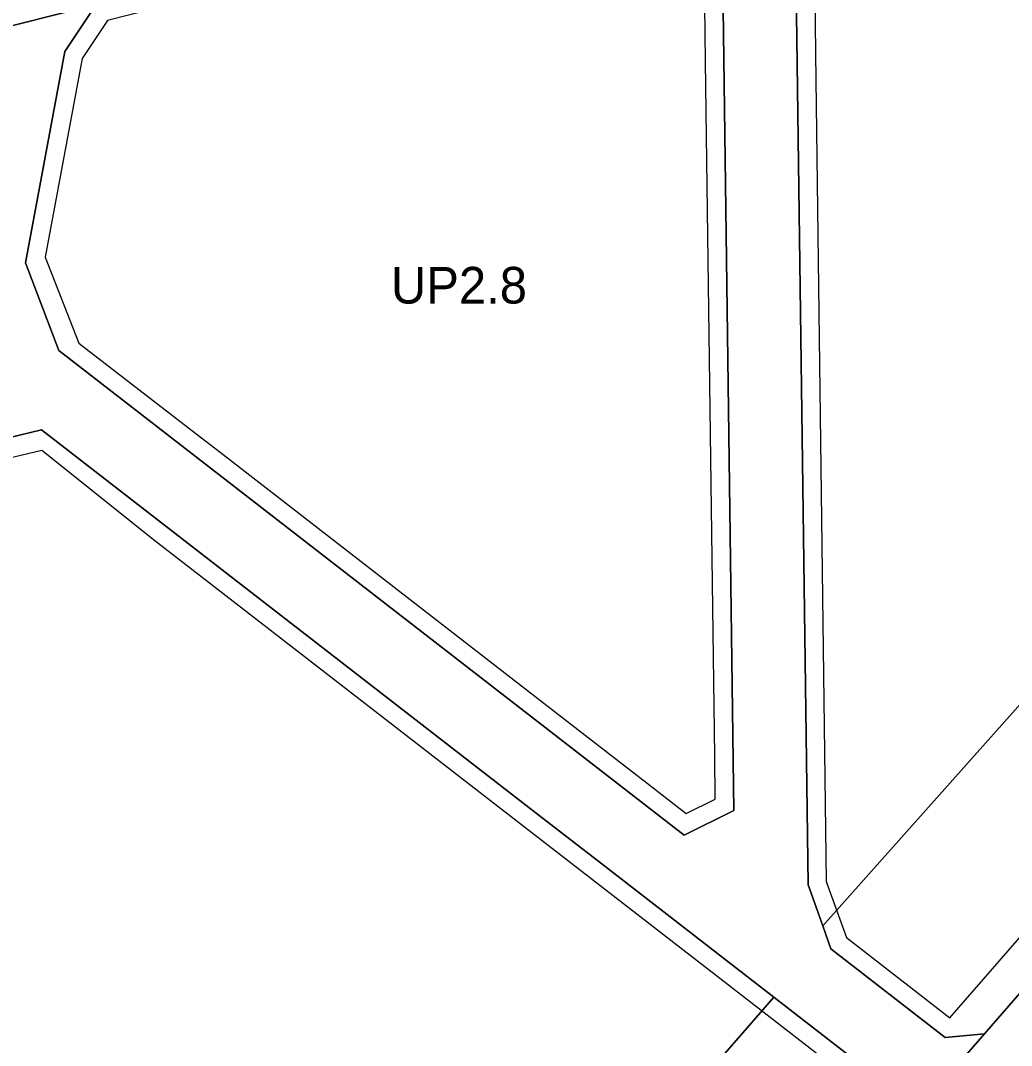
# Model space of a CAD drawing. Extents: x -297746 to -295403, y 27112 to 28877.
# Drawn here: x -296927.6 to -296657.1, y 27465.7 to 27745.5 of the extents above; entities that cross this region are included whole.
import ezdxf

# ---------------------------------------------------------------- set-up
doc = ezdxf.new("R2010")
doc.units = 0
for name, color, linetype in [('linie_rozgraniczajace', 7, 'Continuous'), ('linie_zabudowy_nieprzekraczalne', 7, 'Continuous'), ('linie_zabudowy_obowiazujace', 7, 'Continuous'), ('oznaczenia_przeznaczen', 7, 'Continuous')]:
    doc.layers.add(name, color=color, linetype=linetype)

msp = doc.modelspace()

# ---------------------------------------------------------------- linework, layer by layer
at = {"layer": 'linie_rozgraniczajace'}
for points in [[(-296434.505, 27869.975), (-296706.45, 27800.862), (-296746.32, 27790.729), (-296906.963, 27749.902), (-296939.511, 27741.63), (-296994.696, 27727.605), (-296995.426, 27722.859), (-296995.977, 27720.526), (-296996.722, 27717.999), (-296996.986, 27717.325), (-296988.793, 27710.975), (-297001.433, 27695.468), (-297009.248, 27701.525), (-297010.984, 27700.354), (-297012.53, 27699.459), (-297013.954, 27698.747), (-297015.744, 27697.933), (-297017.209, 27697.364), (-297018.714, 27696.855), (-297020.158, 27696.448), (-297021.212, 27696.201), (-297026.982, 27695.447)], [(-296716.282, 27788.045), (-296712.625, 27509.58), (-296708.605, 27498.319), (-296706.381, 27492.089), (-296675.19, 27467.914), (-296664.406, 27468.917), (-296687.895, 27441.898)], [(-296939.511, 27741.63), (-296906.963, 27749.902), (-296915.532, 27737.059), (-296926.254, 27679.375), (-296917.139, 27655.438), (-296746.434, 27523.132), (-296732.893, 27529.874), (-296736.217, 27782.978)], [(-296455.785, 27708.884), (-296664.406, 27468.917), (-296675.19, 27467.914), (-296706.381, 27492.089), (-296708.605, 27498.319), (-296497.72, 27735.144)], [(-296687.895, 27441.898), (-296664.406, 27468.917), (-296455.785, 27708.884)], [(-296689.133, 27453.416), (-296721.993, 27478.885), (-296770.075, 27516.152), (-296785.976, 27528.476), (-296921.836, 27633.775), (-296936.933, 27630.084), (-296943.148, 27617.146), (-296946.215, 27611.86), (-296949.135, 27607.394), (-296953.049, 27602.075), (-296956.43, 27597.979), (-296960.032, 27594.03), (-296966.95, 27587.428), (-296982.075, 27575.569), (-297001.954, 27560.346), (-297049.986, 27523.564), (-297052.341, 27520.813), (-297060.445, 27511.192), (-297068.206, 27501.892), (-297073.909, 27495.072), (-297080.658, 27487.647), (-297088.887, 27477.865), (-297098.677, 27464.98)], [(-297098.677, 27464.98), (-297088.887, 27477.865), (-297080.658, 27487.647), (-297073.909, 27495.072), (-297068.206, 27501.892), (-297060.445, 27511.192), (-297052.341, 27520.813), (-297049.986, 27523.564), (-297001.954, 27560.346), (-296982.075, 27575.569), (-296966.95, 27587.428), (-296960.032, 27594.03), (-296956.43, 27597.979), (-296953.049, 27602.075), (-296949.135, 27607.394), (-296946.215, 27611.86), (-296943.148, 27617.146), (-296936.933, 27630.084), (-296921.836, 27633.775), (-296785.976, 27528.476), (-296770.075, 27516.152), (-296721.993, 27478.885), (-296853.18, 27327.985)], [(-296853.18, 27327.985), (-296721.993, 27478.885), (-296689.133, 27453.416)]]:
    msp.add_lwpolyline(points, dxfattribs=at)
for points in [[(-296708.605, 27498.319), (-296712.625, 27509.58), (-296716.282, 27788.045), (-296706.45, 27800.862), (-296434.505, 27869.975), (-296420.556, 27861.932), (-296445.171, 27819.646), (-296445.951, 27818.307), (-296482.154, 27756.115), (-296497.72, 27735.144)], [(-296746.434, 27523.132), (-296917.139, 27655.438), (-296926.254, 27679.375), (-296915.532, 27737.059), (-296906.963, 27749.902), (-296746.32, 27790.729), (-296736.217, 27782.978), (-296732.893, 27529.874)]]:
    msp.add_lwpolyline(points, close=True, dxfattribs=at)
at = {"layer": 'linie_zabudowy_nieprzekraczalne'}
for points in [[(-296655.075, 27808.761), (-296703.535, 27796.445), (-296711.257, 27786.379), (-296710.61, 27737.164), (-296710.6, 27736.383), (-296707.633, 27510.479), (-296702.161, 27495.148), (-296673.896, 27473.241), (-296648.812, 27502.094)], [(-296873.104, 27627.639), (-296781.896, 27556.948), (-296755.716, 27536.657), (-296745.85, 27529.009), (-296737.931, 27532.952), (-296738.087, 27544.856), (-296738.528, 27578.409), (-296740.575, 27734.304), (-296741.182, 27780.49), (-296747.436, 27785.287), (-296791.663, 27774.047), (-296845.078, 27760.472)], [(-296737.15, 27484.311), (-296890.92, 27603.492)], [(-296737.15, 27484.311), (-296890.92, 27603.492)]]:
    msp.add_lwpolyline(points, dxfattribs=at)
at = {"layer": 'linie_zabudowy_obowiazujace'}
for points in [[(-296845.078, 27760.472), (-296855.407, 27757.847), (-296903.867, 27745.531), (-296910.801, 27735.139), (-296920.886, 27680.878), (-296911.711, 27657.403), (-296879.704, 27632.755), (-296873.104, 27627.639)], [(-296890.92, 27603.492), (-296921.794, 27628.095), (-296934.887, 27625.004), (-296940.281, 27613.119), (-296948.897, 27599.591), (-296957.817, 27590.693), (-296957.727, 27590.784), (-296959.603, 27588.951), (-296979.191, 27571.961), (-296997.864, 27556.514), (-297033.238, 27529.905), (-297046.359, 27519.012), (-297072.903, 27489.098)], [(-296708.383, 27462.014), (-296737.15, 27484.311)]]:
    msp.add_lwpolyline(points, dxfattribs=at)

# ---------------------------------------------------------------- texts
at = {"layer": 'oznaczenia_przeznaczen'}
msp.add_text('UP2.8', height=10, dxfattribs=at).set_placement((-296826.497, 27668.228))

doc.saveas('drawing.dxf')
